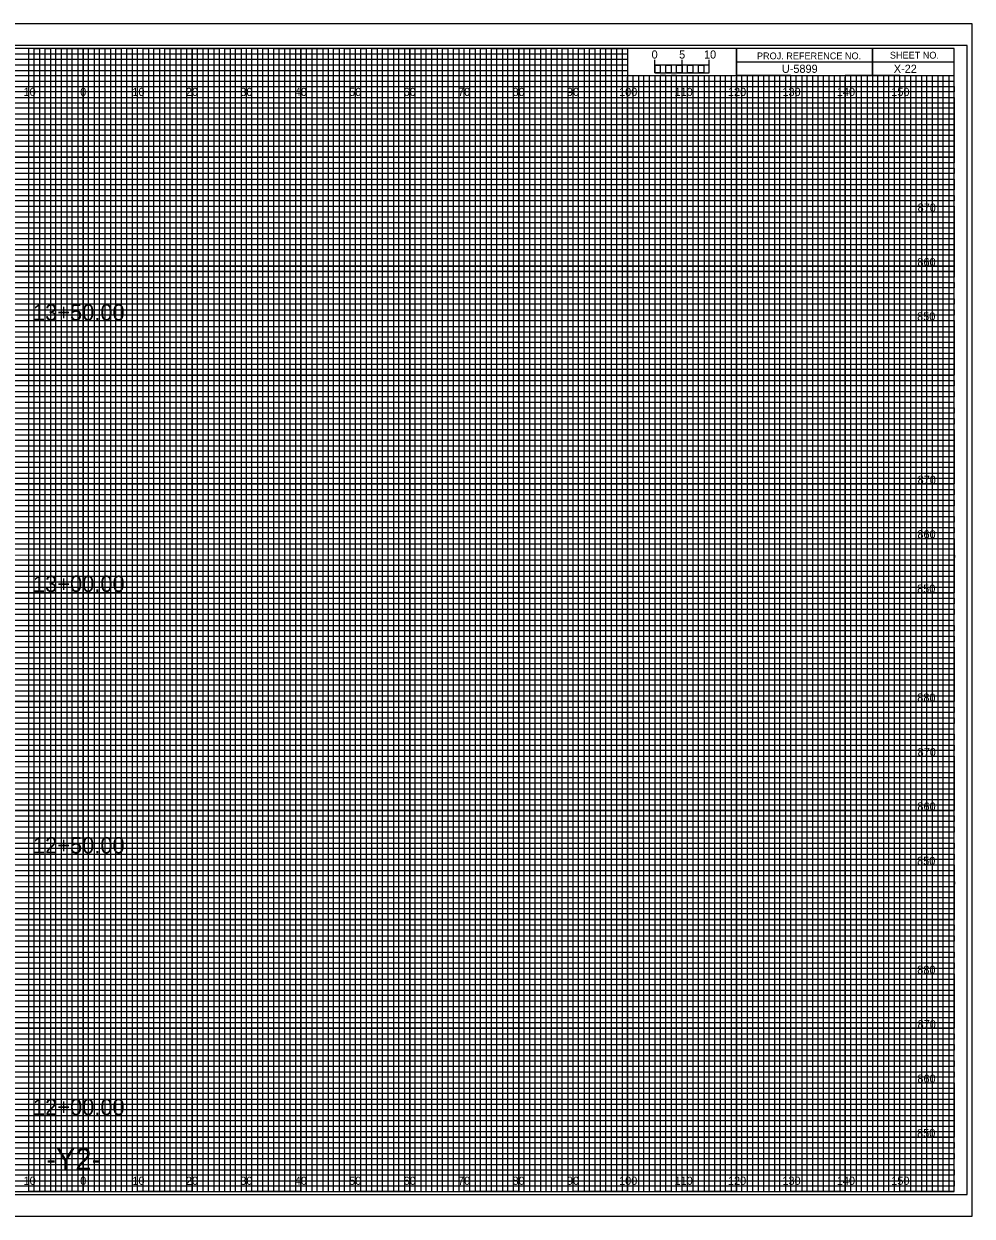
# Model space of a CAD drawing. Extents: x -13 to 323, y 216 to 434.
# Drawn here: x 149.1 to 323.3, y 215.5 to 434.5 of the extents above; entities that cross this region are included whole.
import ezdxf

# ---------------------------------------------------------------- set-up
doc = ezdxf.new("R2010")
doc.units = 0
for name, color, linetype in [('Prop XS Alignment Label', 7, 'Continuous'), ('Prop XS Bar Scale Labels', 7, 'Continuous'), ('Prop XS Elevation Labels', 7, 'Continuous'), ('Prop XS Offset Labels', 7, 'Continuous'), ('Prop XS Project Number', 7, 'Continuous'), ('Prop XS Sheet Number', 7, 'Continuous'), ('Prop XS Station Labels', 7, 'Continuous'), ('Sheet Cross Section CELL', 7, 'Continuous'), ('Sheet Cross Section Grid Major CELL', 7, 'Continuous'), ('Sheet Cross Section Grid Middle CELL', 7, 'Continuous'), ('Sheet Cross Section Grid Minor 1 CELL', 7, 'Continuous'), ('Sheet Cross Section Grid Minor 2 CELL', 7, 'Continuous'), ('Sheet Cross Section Scale CELL', 7, 'Continuous'), ('Sheet Cutting Line CELL', 7, 'Continuous'), ('Sheet DOT Grid CELL', 7, 'Continuous'), ('Sheet Plot Border Inside CELL', 7, 'Continuous'), ('Sheet Plot Border Outside CELL', 7, 'Continuous')]:
    doc.layers.add(name, color=color, linetype=linetype)

msp = doc.modelspace()

# ---------------------------------------------------------------- linework, layer by layer
at = {"layer": 'Sheet Cross Section CELL'}
for p, q in [((305, 430), (305, 425)), ((305, 425), (305, 430)), ((280, 427.5), (280, 425)), ((320, 427.49), (280, 427.49)), ((280, 425), (320, 425))]:
    msp.add_line(p, q, dxfattribs=at)
for points in [[(320, 430), (0, 430), (0, 220), (320, 220)], [(280, 430), (260, 430), (260, 425.03), (280, 425.03)], [(320, 430), (280, 430), (280, 425), (320, 425)]]:
    msp.add_lwpolyline(points, close=True, dxfattribs=at)
at = {"layer": 'Sheet Cross Section Grid Major CELL'}
for p, q in [((150, 430), (140, 430)), ((150, 220), (150, 430)), ((170, 430), (160, 430)), ((160, 430), (160, 220)), ((170, 220), (170, 430)), ((190, 430), (180, 430)), ((180, 430), (180, 220)), ((190, 220), (190, 430)), ((210, 430), (200, 430)), ((200, 430), (200, 220)), ((210, 220), (210, 430)), ((230, 430), (220, 430)), ((220, 430), (220, 220)), ((230, 220), (230, 430)), ((250, 430), (240, 430)), ((240, 430), (240, 220)), ((250, 220), (250, 430)), ((260, 430), (260, 220)), ((270, 220), (270, 425)), ((290, 425), (280, 425)), ((280, 425), (280, 220)), ((290, 220), (290, 425)), ((310, 425), (300, 425)), ((300, 425), (300, 220)), ((310, 220), (310, 425)), ((160, 220), (150, 220)), ((180, 220), (170, 220)), ((200, 220), (190, 220)), ((220, 220), (210, 220)), ((240, 220), (230, 220)), ((260, 220), (250, 220)), ((280, 220), (270, 220)), ((300, 220), (290, 220)), ((320, 220), (310, 220)), ((320, 220), (320, 220))]:
    msp.add_line(p, q, dxfattribs=at)
for points in [[(0, 420), (320, 420), (320, 410), (0, 410)], [(0, 400), (320, 400), (320, 390), (0, 390)], [(0, 380), (320, 380), (320, 370), (0, 370)], [(0, 360), (320, 360), (320, 350), (0, 350)], [(0, 340), (320, 340), (320, 330), (0, 330)], [(0, 320), (320, 320), (320, 310), (0, 310)], [(0, 300), (320, 300), (320, 290), (0, 290)], [(0, 280), (320, 280), (320, 270), (0, 270)], [(0, 260), (320, 260), (320, 250), (0, 250)], [(0, 240), (320, 240), (320, 230), (0, 230)]]:
    msp.add_lwpolyline(points, dxfattribs=at)
at = {"layer": 'Sheet Cross Section Grid Middle CELL'}
for points in [[(145, 220), (155, 220), (155, 430), (165, 430), (165, 220), (175, 220), (175, 430), (185, 430), (185, 220), (195, 220), (195, 430), (205, 430), (205, 220), (215, 220), (215, 430), (225, 430), (225, 220), (235, 220), (235, 430), (245, 430), (245, 220), (255, 220), (255, 430), (259.93, 430), (260, 430), (260, 425), (264.99, 425), (264.99, 220), (275, 220), (275, 425), (285, 425), (285, 220), (295, 220), (295, 425), (305, 425), (305, 220), (315, 220), (315, 425)], [(0, 425), (275, 425)], [(0, 405), (320, 405), (320, 415), (0, 415)], [(0, 385), (320, 385), (320, 395), (0, 395)], [(0, 365), (320, 365), (320, 375), (0, 375)], [(0, 345), (320, 345), (320, 355), (0, 355)], [(0, 325), (320, 325), (320, 335), (0, 335)], [(0, 305), (320, 305), (320, 315), (0, 315)], [(0, 285), (320, 285), (320, 295), (0, 295)], [(0, 265), (320, 265), (320, 275), (0, 275)], [(0, 245), (320, 245), (320, 255), (0, 255)], [(0, 225), (320, 225), (320, 235), (0, 235)]]:
    msp.add_lwpolyline(points, dxfattribs=at)
at = {"layer": 'Sheet Cross Section Grid Minor 1 CELL'}
for p, q in [((0, 429), (260, 429)), ((260, 427.98), (0, 427.98)), ((260, 429), (260, 427.98)), ((0, 427), (260, 427)), ((260, 425.89), (0, 425.89)), ((260, 427), (260, 425.89)), ((0, 424), (320, 424))]:
    msp.add_line(p, q, dxfattribs=at)
for points in [[(0, 423), (270, 423), (320, 423), (320, 422), (0, 422)], [(0, 421), (320, 421), (320, 419), (0, 419)], [(0, 418), (320, 418), (320, 417), (0, 416.98)], [(0, 416), (320, 416), (320, 414), (0, 414)], [(0, 413), (320, 413), (320, 412), (0, 412)], [(0, 411), (320, 411), (320, 409), (0, 409)], [(0, 408), (320, 408), (320, 407), (0, 407)], [(0, 406), (320, 406), (320, 404), (0, 404)], [(0, 403), (320, 403), (320, 402), (0, 402)], [(0, 401), (320, 401), (320, 399), (0, 399)], [(0, 398), (320, 398), (320, 397), (0, 397)], [(0, 396), (320, 396), (320, 393.95), (320, 393), (320, 392), (0, 392)], [(0, 394), (320, 394), (320, 393), (0, 393)], [(0, 391), (320, 391), (320, 389), (0, 389.03)], [(0, 389.03), (320, 389), (320, 388), (0, 388)], [(0, 387), (320, 387), (320, 386), (0, 386)], [(0, 384), (320, 384), (320, 383), (0, 383)], [(0, 382), (320, 382), (320, 381), (0, 381)], [(-0.07, 378.89), (320, 378.89), (320, 377.88), (-0.07, 377.88)], [(0, 377), (320, 377), (320, 376), (0, 376)], [(0, 374), (320, 374), (320, 373), (0, 373)], [(0, 372), (320, 372), (320, 371), (0, 371)], [(0, 369), (320, 369), (320, 368), (0, 368)], [(0, 367), (320, 367), (320, 366), (0, 366)], [(0, 364), (320, 364), (320, 363), (0, 363)], [(0, 362), (320, 362), (320, 361), (0, 361)], [(0, 359), (320, 359), (319.99, 357.98), (0, 358)], [(0, 357), (320, 357), (320, 356), (0, 356)], [(0, 354), (320, 354), (320, 353), (0, 353)], [(0, 352), (320, 352), (320, 351), (0, 351)], [(0, 349), (320, 349), (320, 348), (0, 348)], [(0, 347), (320, 347), (320, 346), (0, 346)], [(0, 344), (320, 344), (320, 343), (0, 343)], [(0, 342), (320, 342), (320, 341), (0, 341)], [(0, 339), (320, 339), (320, 338), (0, 338)], [(0, 336.99), (320.07, 336.91), (320, 336), (0, 336)], [(0, 334), (320, 334), (320, 333), (0, 333)], [(0, 332), (320, 332), (320, 331), (0, 331)], [(0, 329), (320, 329), (320, 328), (0, 328)], [(0, 327), (320, 327), (320, 326), (0, 326)], [(0, 324), (320, 324), (320, 323), (0, 323)], [(0, 322), (320, 322), (320, 321), (0, 321)], [(0, 319), (320, 319), (320, 318), (0, 318)], [(0, 317), (320, 317), (320, 316), (0, 316)], [(0, 314), (320, 314), (320, 313), (0, 313)], [(0, 312), (320, 312), (320, 311), (0, 311)], [(0, 309), (320, 309), (320, 308), (0, 308)], [(0, 307), (320, 307), (320, 306), (0, 306)], [(0, 304), (320, 304), (320, 303), (0, 303)], [(0, 302), (320, 302), (320, 301), (0, 301)], [(0, 299), (320, 299), (319.99, 297.98), (0, 298)], [(0, 297), (320, 297), (320, 296), (0, 296)], [(0, 294), (320, 294), (320, 293), (0, 293)], [(0, 292), (320, 292), (320, 291), (0, 291)], [(0, 289), (320, 289), (320, 288), (0, 288)], [(0, 287), (320, 287), (320, 286), (0, 286)], [(0, 284), (320, 284), (320, 283), (0, 283)], [(0, 282), (320, 282), (320, 281), (0, 281)], [(0, 279), (320, 279), (320, 278), (0, 278)], [(0, 276.99), (320.07, 276.91), (320, 276), (0, 276)], [(0, 274), (320, 274), (320, 273), (0, 273)], [(0, 272), (320, 272), (320, 271), (0, 271)], [(0, 269), (320, 269), (320, 268), (0, 268)], [(0, 267), (320, 267), (320, 266), (0, 266)], [(0, 264), (320, 264), (320, 263), (0, 263)], [(0, 262), (320, 262), (320, 261), (0, 261)], [(0, 259), (320, 259), (320, 258), (0, 258)], [(0, 257), (320, 257), (320, 256), (0, 256)], [(0, 254), (320, 254), (320, 253), (0, 253)], [(0, 252), (320, 252), (320, 251), (0, 251)], [(0, 249), (320, 249), (320, 248), (0, 248)], [(0, 247), (320, 247), (320, 246), (0, 246)], [(0, 244), (320, 244), (320, 243), (0, 243)], [(0, 242), (320, 242), (320, 241), (0, 241)], [(0, 239), (320, 239), (320, 238), (0, 238)], [(0, 237), (320, 237), (320, 236), (0, 236)], [(0, 234), (320, 234), (320, 233), (0, 233)], [(0, 232), (320, 232), (320, 231), (0, 231)], [(0, 229), (320, 229), (320, 228), (0, 228)], [(0, 227), (320, 227), (320, 226), (0, 226)], [(0, 224), (320, 224), (320, 223), (0, 223)], [(0, 222), (320, 222), (320, 221), (0, 221)]]:
    msp.add_lwpolyline(points, dxfattribs=at)
at = {"layer": 'Sheet Cross Section Grid Minor 2 CELL'}
for p, q in [((267, 425), (266.01, 425)), ((266.01, 425), (266.01, 220)), ((267, 220), (267, 425)), ((269, 425), (268, 425)), ((268, 425), (268, 220)), ((269, 220), (269, 425)), ((266.01, 220), (265, 220)), ((268, 220), (267, 220))]:
    msp.add_line(p, q, dxfattribs=at)
for points in [[(150, 220), (151, 220), (151, 430), (152, 430), (152, 220)], [(152, 220), (153, 220), (153, 430), (154, 430), (154, 220)], [(155, 220), (156, 220), (156, 430), (157, 430), (157, 220)], [(157, 220), (158, 220), (158, 430), (159, 430), (159, 220)], [(160, 220), (161, 220), (161, 430), (162, 430), (162, 220)], [(162, 220), (163, 220), (163, 430), (164, 430), (164, 220)], [(165, 220), (166, 220), (166, 430), (167, 430), (167, 220)], [(167, 220), (168, 220), (168, 430), (169, 430), (169, 220)], [(170, 220), (171, 220), (171, 430), (172, 430), (172, 220)], [(172, 220), (173, 220), (173, 430), (174, 430), (174, 220)], [(175, 220), (176, 220), (176, 430), (177, 430), (177, 220)], [(177, 220), (178, 220), (178, 430), (179, 430), (179, 220)], [(180, 220), (181, 220), (181, 430), (182, 430), (182, 220)], [(182, 220), (183, 220), (183, 430), (184, 430), (184, 220)], [(185, 220), (186, 220), (186, 430), (187, 430), (187, 220)], [(187, 220), (188, 220), (188, 430), (189, 430), (189, 220)], [(190, 220), (191, 220), (191, 430), (192, 430), (192, 220)], [(192, 220), (193, 220), (193, 430), (194, 430), (194, 220)], [(195, 220), (196, 220), (196, 430), (197, 430), (197, 220)], [(197, 220), (198, 220), (198, 430), (199, 430), (199, 220)], [(200, 220), (201, 220), (201, 430), (202, 430), (202, 220)], [(202, 220), (203, 220), (203, 430), (204, 430), (204, 220)], [(205, 220), (206, 220), (206, 430), (207, 430), (207, 220)], [(207, 220), (208, 220), (208, 430), (209, 430), (209, 220)], [(210, 220), (211, 220), (211, 430), (212, 430), (212, 220)], [(212, 220), (213, 220), (213, 430), (214, 430), (214, 220)], [(215, 220), (216, 220), (216, 430), (217, 430), (217, 220)], [(217, 220), (218, 220), (218, 430), (219, 430), (219, 220)], [(220, 220), (221, 220), (221, 430), (222, 430), (222, 220)], [(222, 220), (223, 220), (223, 430), (224, 430), (224, 220)], [(225, 220), (226, 220), (226, 430), (227, 430), (227, 220)], [(227, 220), (228, 220), (228, 430), (229, 430), (229, 220)], [(230, 220), (231, 220), (231, 430), (232, 430), (232, 220)], [(232, 220), (233, 220), (233, 430), (234, 430), (234, 220)], [(235, 220), (236, 220), (236, 430), (237, 430), (237, 220)], [(237, 220), (238, 220), (238, 430), (239, 430), (239, 220)], [(240, 220), (241, 220), (241, 430), (242, 430), (242, 220)], [(242, 220), (243, 220), (243, 430), (244, 430), (244, 220)], [(245, 220), (246, 220), (246, 430), (247, 430), (247, 220)], [(247, 220), (248, 220), (248, 430), (249, 430), (249, 220)], [(250, 220), (251, 220), (251, 430), (252, 430), (252, 220)], [(252, 220), (253, 220), (253, 430), (254, 430), (254, 220)], [(255, 220), (256, 220), (256, 430), (257, 430), (257, 220)], [(257, 220), (258, 220), (258, 430), (259, 430), (259, 220)], [(260, 220), (261, 220), (261, 425), (262.02, 425), (262.02, 220)], [(262, 220), (263, 220), (263, 425), (263.99, 425), (263.99, 220)], [(270, 220), (270.98, 220), (270.98, 425), (272, 425), (272, 220)], [(272, 220), (273, 220), (273, 425), (274.05, 425), (274.05, 220)], [(275, 220), (276, 220), (276, 425), (277, 425), (277, 220)], [(277, 220), (278, 220), (278, 425), (279, 425), (279, 220)], [(280, 220), (281, 220), (281, 425), (282, 425), (282, 220)], [(282, 220), (283, 220), (283, 425), (284, 425), (284, 220)], [(285, 220), (286, 220), (286, 425), (287, 425), (287, 220)], [(287, 220), (288, 220), (288, 425), (289, 425), (289, 220)], [(290, 220), (291, 220), (291, 425), (292, 425), (292, 220)], [(292, 220), (293, 220), (293, 425), (294, 425), (294, 220)], [(295, 220), (296, 220), (296, 425), (297, 425), (297, 220)], [(297, 220), (298, 220), (298, 425), (299, 425), (299, 220)], [(300, 220), (301, 220), (301, 425), (302, 425), (302, 220)], [(302, 220), (303, 220), (303, 425), (304, 425), (304, 220)], [(305, 220), (306, 220), (306, 425), (307, 425), (307, 220)], [(307, 220), (308, 220), (308, 425), (309, 425), (309, 220)], [(310, 220), (311, 220), (311, 425), (312, 425), (312, 220)], [(312, 220), (313, 220), (313, 425), (314, 425), (314, 220)], [(315, 220), (316, 220), (316, 425), (317, 425), (317, 220)], [(317, 220), (318, 220), (318, 425), (319, 425), (319, 220)]]:
    msp.add_lwpolyline(points, dxfattribs=at)
at = {"layer": 'Sheet Cross Section Scale CELL'}
for p, q in [((265, 425.49), (265, 427.9)), ((265, 426.9), (265, 427.9)), ((270, 425.49), (270, 427.9)), ((275, 425.49), (275, 427.9)), ((275, 426.9), (275, 427.9))]:
    msp.add_line(p, q, dxfattribs=at)
for points in [[(275, 426.9), (265, 426.9), (265, 425.49), (275, 425.49)], [(265, 426.9), (266, 426.9), (266, 425.49), (265, 425.49)], [(267, 426.9), (268, 426.9), (268, 425.49), (267, 425.49)], [(269, 426.9), (270, 426.9), (270, 425.49), (269, 425.49)], [(271, 426.9), (272, 426.9), (272, 425.49), (271, 425.49)], [(273, 426.9), (274, 426.9), (274, 425.49), (273, 425.49)]]:
    msp.add_lwpolyline(points, close=True, dxfattribs=at)
at = {"layer": 'Sheet Cutting Line CELL'}
for p, q in [((323.3, 434.5), (-13.4, 434.5)), ((-13.4, 215.5), (323.3, 215.5))]:
    msp.add_line(p, q, dxfattribs=at)
at = {"layer": 'Sheet DOT Grid CELL'}
for p, q in [((150, 220), (150, 430)), ((160, 220), (160, 430)), ((170, 220), (170, 430)), ((180, 220), (180, 430)), ((190, 220), (190, 430)), ((200, 220), (200, 430)), ((210, 220), (210, 430)), ((220, 220), (220, 430)), ((230, 220), (230, 430)), ((240, 220), (240, 430)), ((250, 220), (250, 430)), ((260, 220), (260, 424.69)), ((270, 220), (270, 424.69)), ((280, 220), (280, 424.69)), ((290, 220), (290, 424.69)), ((300, 220), (300, 424.69)), ((310, 220), (310, 424.69)), ((0, 420), (320, 420)), ((0, 410), (320, 410)), ((0, 400), (320, 400)), ((0, 390), (320, 390)), ((0, 380), (320, 380)), ((0, 370), (320, 370)), ((0, 360), (320, 360)), ((0, 350), (320, 350)), ((0, 340), (320, 340)), ((0, 330), (320, 330)), ((0, 320), (320, 320)), ((0, 310), (320, 310)), ((0, 300), (320, 300)), ((0, 290), (320, 290)), ((0, 280), (320, 280)), ((0, 270), (320, 270)), ((0, 260), (320, 260)), ((0, 250), (320, 250)), ((0, 240), (320, 240)), ((0, 230), (320, 230))]:
    msp.add_line(p, q, dxfattribs=at)
at = {"layer": 'Sheet Plot Border Inside CELL'}
msp.add_lwpolyline([(-10.8, 219.5), (322.4, 219.5), (322.4, 430.5), (-10.8, 430.5)], close=True, dxfattribs=at)
at = {"layer": 'Sheet Plot Border Outside CELL'}
msp.add_lwpolyline([(-13.4, 215.5), (323.3, 215.5), (323.3, 434.5), (-13.4, 434.5)], close=True, dxfattribs=at)

# ---------------------------------------------------------------- texts
at = {"layer": 'Prop XS Alignment Label'}
msp.add_text('-Y2-', height=4, dxfattribs=at).set_placement((153.21, 224))
at = {"layer": 'Prop XS Bar Scale Labels'}
for s, p in [('5', (269.47, 428.12)), ('10', (274.04, 428.12))]:
    msp.add_text(s, height=1.5, dxfattribs=at).set_placement(p)
at = {"layer": 'Prop XS Elevation Labels'}
for s, p in [('870', (313.28, 400)), ('860', (313.24, 390)), ('850', (313.19, 380)), ('870', (313.28, 350)), ('860', (313.24, 340)), ('850', (313.19, 330)), ('880', (313.22, 310)), ('870', (313.28, 300)), ('860', (313.24, 290)), ('850', (313.19, 280)), ('880', (313.22, 260)), ('870', (313.28, 250)), ('860', (313.24, 240)), ('850', (313.19, 230))]:
    msp.add_text(s, height=1.5, dxfattribs=at).set_placement(p)
at = {"layer": 'Prop XS Offset Labels'}
for s, p in [('10', (149.04, 421.25)), ('0', (159.45, 421.25)), ('0', (159.45, 421.25)), ('10', (169.04, 421.25)), ('20', (178.86, 421.25)), ('30', (188.86, 421.25)), ('40', (198.86, 421.25)), ('50', (208.86, 421.25)), ('60', (218.86, 421.25)), ('70', (228.86, 421.25)), ('80', (238.86, 421.25)), ('90', (248.86, 421.25)), ('100', (258.44, 421.25)), ('110', (268.62, 421.25)), ('120', (278.44, 421.25)), ('130', (288.44, 421.25)), ('140', (298.44, 421.25)), ('150', (308.44, 421.25)), ('10', (149.04, 221.25)), ('0', (159.45, 221.25)), ('0', (159.45, 221.25)), ('10', (169.04, 221.25)), ('20', (178.86, 221.25)), ('30', (188.86, 221.25)), ('40', (198.86, 221.25)), ('50', (208.86, 221.25)), ('60', (218.86, 221.25)), ('70', (228.86, 221.25)), ('80', (238.86, 221.25)), ('90', (248.86, 221.25)), ('100', (258.44, 221.25)), ('110', (268.62, 221.25)), ('120', (278.44, 221.25)), ('130', (288.44, 221.25)), ('140', (298.44, 221.25)), ('150', (308.44, 221.25))]:
    msp.add_text(s, height=1.5, dxfattribs=at).set_placement(p)
at = {"layer": 'Prop XS Project Number'}
msp.add_text('U-5899', height=1.5, dxfattribs=at).set_placement((288.34, 425.5))
at = {"layer": 'Prop XS Sheet Number'}
msp.add_text('X-22', height=1.5, dxfattribs=at).set_placement((308.9, 425.5))
at = {"layer": 'Prop XS Station Labels'}
for s, p in [('13+50.00', (150.77, 380.01)), ('13+00.00', (150.77, 330.15)), ('12+50.00', (150.77, 282.13)), ('12+00.00', (150.77, 234.05))]:
    msp.add_text(s, height=3, dxfattribs=at).set_placement(p)
at = {"layer": 'Sheet Cross Section CELL'}
for s, p in [('PROJ. REFERENCE NO.', (283.77, 427.99)), ('SHEET NO.', (308.19, 428.12))]:
    msp.add_text(s, height=1.25, dxfattribs=at).set_placement(p)
at = {"layer": 'Sheet Cross Section Scale CELL'}
msp.add_text('0', height=1.5, dxfattribs=at).set_placement((264.41, 428.12))

doc.saveas('drawing.dxf')
